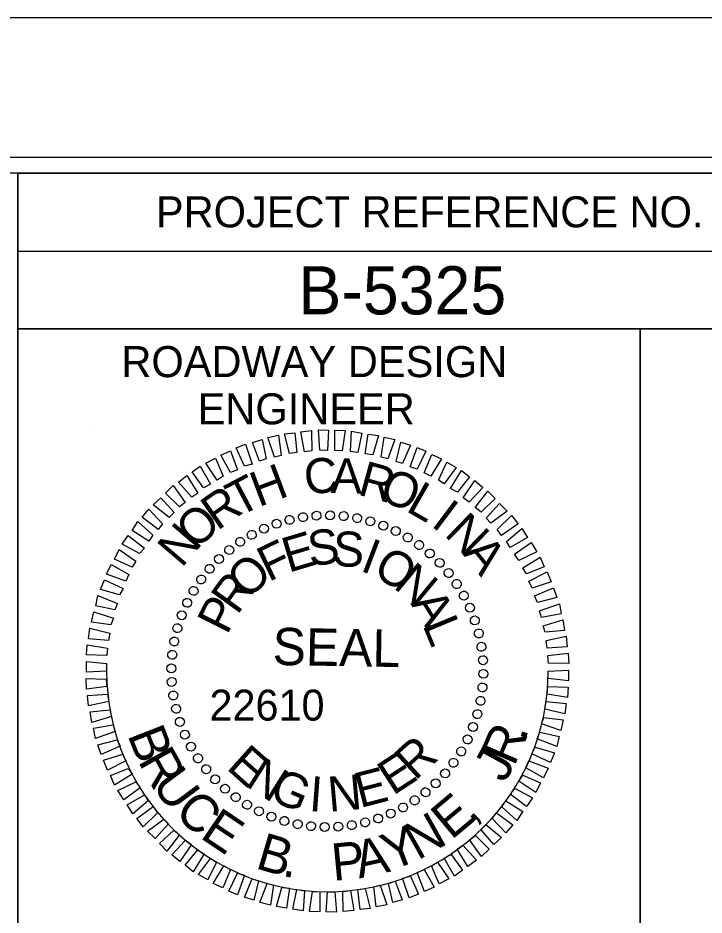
# Model space of a CAD drawing. Extents: x 10033 to 11717, y 9950 to 11050.
# Drawn here: x 11500 to 11610.3, y 10905.6 to 11050 of the extents above; entities that cross this region are included whole.
import ezdxf

# ---------------------------------------------------------------- set-up
doc = ezdxf.new("R2010")
doc.units = 0
for name, color, linetype in [('Default', 7, 'Continuous'), ('Scratch_Level_0', 7, 'Continuous'), ('Sheet Cutting Line CELL', 7, 'Continuous'), ('Sheet Data Field CELL', 7, 'Continuous'), ('Sheet PE Seal CELL', 7, 'Continuous'), ('Sheet Plot Border Inside CELL', 7, 'Continuous'), ('Sheet Plot Border Outside CELL', 7, 'Continuous'), ('Sheet Profile CELL', 7, 'Continuous'), ('Sheet Profile Grid Major CELL', 7, 'Continuous')]:
    doc.layers.add(name, color=color, linetype=linetype)

msp = doc.modelspace()

# ---------------------------------------------------------------- linework, layer by layer
at = {"layer": 'Scratch_Level_0'}
msp.add_arc((11549.72, 10944.9), 35.5, 180, 360, dxfattribs=at)
at = {"layer": 'Sheet Cutting Line CELL'}
msp.add_line((11717, 11050), (10033, 11050), dxfattribs=at)
at = {"layer": 'Sheet PE Seal CELL'}
for p, q in [((11511.62, 10984.6), (11511.62, 10984.6)), ((11545.82, 10969.65), (11545.82, 10969.65)), ((11547.97, 10969.95), (11547.97, 10969.95)), ((11550.17, 10970), (11550.17, 10970)), ((11552.37, 10969.85), (11552.37, 10969.85)), ((11554.52, 10969.5), (11554.52, 10969.5)), ((11541.52, 10968.65), (11541.52, 10968.65)), ((11543.62, 10969.25), (11543.62, 10969.25)), ((11556.62, 10969.05), (11556.62, 10969.05)), ((11558.72, 10968.35), (11558.72, 10968.35)), ((11537.57, 10966.85), (11537.57, 10966.85)), ((11539.52, 10967.85), (11539.52, 10967.85)), ((11560.72, 10967.45), (11560.72, 10967.45)), ((11535.67, 10965.7), (11535.67, 10965.7)), ((11562.67, 10966.45), (11562.67, 10966.45)), ((11564.47, 10965.2), (11564.47, 10965.2)), ((11533.92, 10964.45), (11533.92, 10964.45)), ((11566.22, 10963.85), (11566.22, 10963.85)), ((11532.27, 10962.95), (11532.27, 10962.95)), ((11567.77, 10962.35), (11567.77, 10962.35)), ((11530.77, 10961.4), (11530.77, 10961.4)), ((11529.42, 10959.65), (11529.42, 10959.65)), ((11569.27, 10960.7), (11569.27, 10960.7)), ((11570.52, 10958.95), (11570.52, 10958.95)), ((11528.17, 10957.85), (11528.17, 10957.85)), ((11571.67, 10957.05), (11571.67, 10957.05)), ((11527.17, 10955.9), (11527.17, 10955.9)), ((11572.67, 10955.1), (11572.67, 10955.1)), ((11526.27, 10953.9), (11526.27, 10953.9)), ((11573.47, 10953.1), (11573.47, 10953.1)), ((11525.57, 10951.8), (11525.57, 10951.8)), ((11574.07, 10951), (11574.07, 10951)), ((11525.12, 10949.7), (11525.12, 10949.7)), ((11574.47, 10948.8), (11574.47, 10948.8)), ((11524.77, 10947.55), (11524.77, 10947.55)), ((11574.77, 10946.65), (11574.77, 10946.65)), ((11524.62, 10945.35), (11524.62, 10945.35)), ((11549.72, 10944.9), (11549.72, 10944.9)), ((11574.82, 10944.45), (11574.82, 10944.45)), ((11524.67, 10943.15), (11524.67, 10943.15)), ((11574.67, 10942.25), (11574.67, 10942.25)), ((11524.97, 10941), (11524.97, 10941)), ((11574.32, 10940.1), (11574.32, 10940.1)), ((11525.37, 10938.8), (11525.37, 10938.8)), ((11573.87, 10938), (11573.87, 10938)), ((11525.97, 10936.7), (11525.97, 10936.7)), ((11573.17, 10935.9), (11573.17, 10935.9)), ((11526.77, 10934.7), (11526.77, 10934.7)), ((11572.27, 10933.9), (11572.27, 10933.9)), ((11527.77, 10932.75), (11527.77, 10932.75)), ((11528.92, 10930.85), (11528.92, 10930.85)), ((11571.27, 10931.95), (11571.27, 10931.95)), ((11530.17, 10929.1), (11530.17, 10929.1)), ((11570.02, 10930.15), (11570.02, 10930.15)), ((11568.67, 10928.4), (11568.67, 10928.4)), ((11531.67, 10927.45), (11531.67, 10927.45)), ((11567.17, 10926.85), (11567.17, 10926.85)), ((11533.22, 10925.95), (11533.22, 10925.95)), ((11565.52, 10925.35), (11565.52, 10925.35)), ((11534.97, 10924.6), (11534.97, 10924.6)), ((11536.77, 10923.35), (11536.77, 10923.35)), ((11563.77, 10924.1), (11563.77, 10924.1)), ((11538.72, 10922.35), (11538.72, 10922.35)), ((11559.92, 10921.95), (11559.92, 10921.95)), ((11561.87, 10922.95), (11561.87, 10922.95)), ((11540.72, 10921.45), (11540.72, 10921.45)), ((11542.82, 10920.75), (11542.82, 10920.75)), ((11555.82, 10920.55), (11555.82, 10920.55)), ((11557.92, 10921.15), (11557.92, 10921.15)), ((11544.92, 10920.3), (11544.92, 10920.3)), ((11547.07, 10919.95), (11547.07, 10919.95)), ((11549.27, 10919.8), (11549.27, 10919.8)), ((11551.47, 10919.85), (11551.47, 10919.85)), ((11553.62, 10920.15), (11553.62, 10920.15))]:
    msp.add_line(p, q, dxfattribs=at)
for points in [[(11541.22, 10979.35), (11540.17, 10982.5), (11541.87, 10982.85), (11542.27, 10979.6)], [(11543.62, 10979.9), (11542.82, 10983.1), (11544.47, 10983.25), (11544.82, 10980.05)], [(11546.02, 10980.2), (11545.47, 10983.4), (11547.17, 10983.6), (11547.22, 10980.35)], [(11548.52, 10980.45), (11548.27, 10983.7), (11549.92, 10983.65), (11549.72, 10980.4)], [(11550.92, 10980.4), (11550.92, 10983.65), (11552.57, 10983.6), (11552.12, 10980.35)], [(11553.42, 10980.25), (11553.62, 10983.5), (11555.27, 10983.2), (11554.62, 10980.05)], [(11555.82, 10979.85), (11556.27, 10983.05), (11557.92, 10982.8), (11557.02, 10979.7)], [(11558.37, 10979.3), (11558.87, 10982.55), (11560.57, 10982.15), (11559.42, 10979.05)], [(11536.37, 10977.9), (11535.07, 10980.8), (11536.57, 10981.4), (11537.62, 10978.2)], [(11538.82, 10978.7), (11537.67, 10981.7), (11539.22, 10982.15), (11539.87, 10979.05)], [(11560.77, 10978.65), (11561.52, 10981.75), (11563.07, 10981.25), (11561.82, 10978.3)], [(11534.17, 10976.85), (11532.57, 10979.65), (11534.12, 10980.35), (11535.27, 10977.3)], [(11563.02, 10977.75), (11564.17, 10980.9), (11565.57, 10980.3), (11564.17, 10977.4)], [(11565.27, 10976.8), (11566.52, 10979.75), (11568.07, 10979.05), (11566.37, 10976.25)], [(11532.02, 10975.65), (11530.17, 10978.35), (11531.72, 10979.15), (11532.97, 10976.25)], [(11567.57, 10975.65), (11568.92, 10978.5), (11570.42, 10977.65), (11568.52, 10975.05)], [(11529.82, 10974.4), (11527.97, 10976.95), (11529.27, 10977.9), (11530.92, 10975)], [(11569.52, 10974.3), (11571.27, 10977.2), (11572.57, 10976.15), (11570.62, 10973.7)], [(11527.92, 10972.9), (11525.77, 10975.3), (11527.12, 10976.35), (11528.87, 10973.55)], [(11571.57, 10972.8), (11573.42, 10975.55), (11574.72, 10974.45), (11572.52, 10972.1)], [(11525.92, 10971.35), (11523.72, 10973.55), (11524.92, 10974.75), (11526.87, 10972.05)], [(11573.47, 10971.25), (11575.52, 10973.85), (11576.72, 10972.65), (11574.42, 10970.5)], [(11524.27, 10969.6), (11521.72, 10971.65), (11522.97, 10972.8), (11525.07, 10970.4)], [(11522.52, 10967.7), (11519.92, 10969.65), (11521.02, 10970.95), (11523.22, 10968.6)], [(11575.27, 10969.5), (11577.42, 10971.85), (11578.62, 10970.65), (11576.02, 10968.7)], [(11577.02, 10967.7), (11579.32, 10969.95), (11580.37, 10968.6), (11577.72, 10966.7)], [(11521.02, 10965.8), (11518.32, 10967.5), (11519.27, 10968.95), (11521.67, 10966.75)], [(11519.52, 10963.8), (11516.72, 10965.3), (11517.72, 10966.7), (11520.32, 10964.7)], [(11578.52, 10965.75), (11580.97, 10967.85), (11581.92, 10966.4), (11579.12, 10964.8)], [(11579.82, 10963.7), (11582.47, 10965.6), (11583.42, 10964.1), (11580.52, 10962.7)], [(11518.32, 10961.65), (11515.47, 10962.9), (11516.22, 10964.45), (11518.92, 10962.6)], [(11581.12, 10961.5), (11583.92, 10963.25), (11584.57, 10961.7), (11581.72, 10960.55)], [(11517.32, 10959.35), (11514.22, 10960.5), (11514.97, 10962.05), (11517.82, 10960.45)], [(11582.12, 10959.35), (11585.07, 10960.85), (11585.72, 10959.25), (11582.62, 10958.25)], [(11516.32, 10957.15), (11513.22, 10958.05), (11513.87, 10959.6), (11516.87, 10958.2)], [(11583.02, 10957), (11586.07, 10958.3), (11586.62, 10956.75), (11583.52, 10955.95)], [(11515.57, 10954.75), (11512.47, 10955.4), (11512.82, 10957.05), (11515.97, 10955.8)], [(11583.82, 10954.6), (11587.02, 10955.75), (11587.32, 10954.1), (11584.17, 10953.55)], [(11514.92, 10952.35), (11511.82, 10952.75), (11512.17, 10954.45), (11515.32, 10953.4)], [(11584.42, 10952.2), (11587.57, 10953.15), (11587.87, 10951.45), (11584.72, 10951.15)], [(11514.52, 10949.8), (11511.32, 10950.1), (11511.52, 10951.8), (11514.77, 10951)], [(11584.87, 10949.8), (11588.12, 10950.5), (11588.27, 10948.8), (11585.07, 10948.6)], [(11514.27, 10947.4), (11511.02, 10947.5), (11511.12, 10949.15), (11514.37, 10948.6)], [(11514.22, 10944.9), (11510.97, 10944.75), (11510.97, 10946.45), (11514.22, 10946.1)], [(11585.17, 10947.4), (11588.42, 10947.8), (11588.52, 10946.1), (11585.27, 10946.2)], [(11585.22, 10944.9), (11588.47, 10945.05), (11588.47, 10943.35), (11585.22, 10943.7)], [(11514.27, 10942.4), (11511.02, 10942), (11510.92, 10943.7), (11514.17, 10943.6)], [(11585.17, 10942.4), (11588.42, 10942.3), (11588.32, 10940.65), (11585.07, 10941.2)], [(11514.57, 10940), (11511.32, 10939.3), (11511.17, 10941), (11514.37, 10941.2)], [(11584.92, 10940), (11588.12, 10939.7), (11587.92, 10938), (11584.67, 10938.8)], [(11515.02, 10937.6), (11511.87, 10936.65), (11511.57, 10938.35), (11514.72, 10938.65)], [(11584.52, 10937.45), (11587.62, 10937.05), (11587.27, 10935.35), (11584.12, 10936.4)], [(11515.62, 10935.2), (11512.42, 10934.05), (11512.12, 10935.7), (11515.27, 10936.25)], [(11583.87, 10935.05), (11586.97, 10934.4), (11586.62, 10932.75), (11583.47, 10934)], [(11516.42, 10932.8), (11513.37, 10931.5), (11512.82, 10933.05), (11515.92, 10933.85)], [(11583.12, 10932.65), (11586.22, 10931.75), (11585.57, 10930.2), (11582.57, 10931.6)], [(11517.32, 10930.45), (11514.37, 10928.95), (11513.72, 10930.55), (11516.82, 10931.55)], [(11518.32, 10928.3), (11515.52, 10926.55), (11514.87, 10928.1), (11517.72, 10929.25)], [(11582.12, 10930.45), (11585.22, 10929.3), (11584.47, 10927.75), (11581.62, 10929.35)], [(11581.12, 10928.15), (11583.97, 10926.9), (11583.22, 10925.35), (11580.52, 10927.2)], [(11519.62, 10926.1), (11516.97, 10924.2), (11516.02, 10925.7), (11518.92, 10927.1)], [(11520.92, 10924.05), (11518.47, 10921.95), (11517.52, 10923.4), (11520.32, 10925)], [(11579.92, 10926), (11582.72, 10924.5), (11581.72, 10923.1), (11579.12, 10925.1)], [(11578.42, 10924), (11581.12, 10922.3), (11580.17, 10920.85), (11577.77, 10923.05)], [(11522.42, 10922.1), (11520.12, 10919.85), (11519.07, 10921.2), (11521.72, 10923.1)], [(11576.92, 10922.1), (11579.52, 10920.15), (11578.42, 10918.85), (11576.22, 10921.2)], [(11524.17, 10920.3), (11522.02, 10917.95), (11520.82, 10919.15), (11523.42, 10921.1)], [(11525.97, 10918.55), (11523.92, 10915.95), (11522.72, 10917.15), (11525.02, 10919.3)], [(11575.17, 10920.2), (11577.72, 10918.15), (11576.47, 10917), (11574.37, 10919.4)], [(11527.87, 10917), (11526.02, 10914.25), (11524.72, 10915.35), (11526.92, 10917.7)], [(11573.52, 10918.45), (11575.72, 10916.25), (11574.52, 10915.05), (11572.57, 10917.75)], [(11529.92, 10915.5), (11528.17, 10912.6), (11526.87, 10913.65), (11528.82, 10916.1)], [(11571.52, 10916.9), (11573.67, 10914.5), (11572.32, 10913.45), (11570.57, 10916.25)], [(11531.87, 10914.15), (11530.52, 10911.3), (11529.02, 10912.15), (11530.92, 10914.75)], [(11569.62, 10915.4), (11571.47, 10912.85), (11570.17, 10911.9), (11568.52, 10914.8)], [(11534.17, 10913), (11532.92, 10910.05), (11531.37, 10910.75), (11533.07, 10913.55)], [(11567.42, 10914.15), (11569.27, 10911.45), (11567.72, 10910.65), (11566.47, 10913.55)], [(11536.42, 10912.05), (11535.27, 10908.9), (11533.87, 10909.5), (11535.27, 10912.4)], [(11563.07, 10911.9), (11564.37, 10909), (11562.87, 10908.4), (11561.82, 10911.6)], [(11565.27, 10912.95), (11566.87, 10910.15), (11565.32, 10909.45), (11564.17, 10912.5)], [(11538.67, 10911.15), (11537.92, 10908.05), (11536.37, 10908.55), (11537.62, 10911.5)], [(11541.07, 10910.5), (11540.57, 10907.25), (11538.87, 10907.65), (11540.02, 10910.75)], [(11558.22, 10910.45), (11559.27, 10907.3), (11557.57, 10906.95), (11557.17, 10910.2)], [(11560.62, 10911.1), (11561.77, 10908.1), (11560.22, 10907.65), (11559.57, 10910.75)], [(11543.62, 10909.95), (11543.17, 10906.75), (11541.52, 10907), (11542.42, 10910.1)], [(11546.02, 10909.55), (11545.82, 10906.3), (11544.17, 10906.6), (11544.82, 10909.75)], [(11548.52, 10909.4), (11548.52, 10906.15), (11546.87, 10906.2), (11547.32, 10909.45)], [(11550.92, 10909.35), (11551.17, 10906.1), (11549.52, 10906.15), (11549.72, 10909.4)], [(11553.42, 10909.6), (11553.97, 10906.4), (11552.27, 10906.2), (11552.22, 10909.45)], [(11555.82, 10909.9), (11556.62, 10906.7), (11554.97, 10906.55), (11554.62, 10909.75)]]:
    msp.add_lwpolyline(points, close=True, dxfattribs=at)
for centre, major_axis in [((11543.65, 10969.23), (-0.174, 0.699)), ((11545.8, 10969.67), (-0.113, 0.711)), ((11547.97, 10969.91), (-0.05, 0.718)), ((11550.16, 10969.97), (0.013, 0.72)), ((11552.34, 10969.84), (0.075, 0.716)), ((11554.51, 10969.51), (0.137, 0.707)), ((11556.63, 10969), (0.198, 0.692)), ((11539.52, 10967.81), (-0.293, 0.658)), ((11541.56, 10968.61), (-0.234, 0.681)), ((11558.71, 10968.31), (0.258, 0.672)), ((11560.72, 10967.44), (0.316, 0.647)), ((11537.56, 10966.83), (-0.349, 0.63)), ((11562.64, 10966.39), (0.371, 0.617)), ((11533.94, 10964.39), (-0.453, 0.56)), ((11535.7, 10965.69), (-0.403, 0.597)), ((11564.46, 10965.19), (0.423, 0.582)), ((11532.3, 10962.94), (-0.5, 0.518)), ((11566.18, 10963.82), (0.472, 0.543)), ((11567.76, 10962.32), (0.518, 0.5)), ((11530.79, 10961.35), (-0.543, 0.472)), ((11569.21, 10960.68), (0.56, 0.453)), ((11529.43, 10959.64), (-0.582, 0.423)), ((11570.51, 10958.92), (0.597, 0.403)), ((11528.22, 10957.81), (-0.617, 0.371)), ((11527.18, 10955.89), (-0.647, 0.316)), ((11571.66, 10957.05), (0.63, 0.349)), ((11572.63, 10955.1), (0.658, 0.293)), ((11526.31, 10953.88), (-0.672, 0.258)), ((11573.43, 10953.06), (0.681, 0.234)), ((11525.61, 10951.81), (-0.692, 0.198)), ((11574.06, 10950.96), (0.699, 0.174)), ((11525.1, 10949.68), (-0.707, 0.137)), ((11574.49, 10948.82), (0.711, 0.113)), ((11524.78, 10947.52), (-0.716, 0.075)), ((11574.74, 10946.65), (0.718, 0.05)), ((11524.64, 10945.33), (-0.72, 0.013)), ((11574.8, 10944.46), (0.72, -0.013)), ((11524.7, 10943.15), (-0.718, -0.05)), ((11574.66, 10942.27), (0.716, -0.075)), ((11524.95, 10940.97), (-0.711, -0.113)), ((11574.34, 10940.11), (0.707, -0.137)), ((11525.39, 10938.83), (-0.699, -0.174)), ((11573.83, 10937.98), (0.692, -0.198)), ((11526.01, 10936.73), (-0.681, -0.234)), ((11573.14, 10935.91), (0.672, -0.258)), ((11526.81, 10934.69), (-0.658, -0.293)), ((11527.79, 10932.74), (-0.63, -0.349)), ((11572.26, 10933.9), (0.647, -0.316)), ((11571.22, 10931.98), (0.617, -0.371)), ((11528.93, 10930.87), (-0.597, -0.403)), ((11570.01, 10930.15), (0.582, -0.423)), ((11530.23, 10929.11), (-0.56, -0.453)), ((11568.65, 10928.44), (0.543, -0.472)), ((11531.68, 10927.47), (-0.518, -0.5)), ((11567.14, 10926.85), (0.5, -0.518)), ((11533.27, 10925.97), (-0.472, -0.543)), ((11565.5, 10925.4), (0.453, -0.56)), ((11534.98, 10924.61), (-0.423, -0.582)), ((11563.75, 10924.1), (0.403, -0.597)), ((11536.8, 10923.4), (-0.371, -0.617)), ((11561.88, 10922.96), (0.349, -0.63)), ((11538.73, 10922.35), (-0.316, -0.647)), ((11540.73, 10921.48), (-0.258, -0.672)), ((11557.89, 10921.18), (0.234, -0.681)), ((11559.92, 10921.98), (0.293, -0.658)), ((11542.81, 10920.79), (-0.198, -0.692)), ((11544.94, 10920.28), (-0.137, -0.707)), ((11547.1, 10919.95), (-0.075, -0.716)), ((11549.28, 10919.82), (-0.013, -0.72)), ((11551.47, 10919.88), (0.05, -0.718)), ((11553.64, 10920.12), (0.113, -0.711)), ((11555.79, 10920.56), (0.174, -0.699))]:
    msp.add_ellipse(centre, major_axis=major_axis, ratio=0.999708, dxfattribs=at)
at = {"layer": 'Sheet Plot Border Inside CELL'}
msp.add_lwpolyline([(11712.5, 11027.55), (10046, 11027.55), (10046, 9972.45), (11712.5, 9972.45)], close=True, dxfattribs=at)
at = {"layer": 'Sheet Plot Border Outside CELL'}
msp.add_lwpolyline([(11717, 11050), (10033, 11050), (10033, 9950), (11717, 9950)], close=True, dxfattribs=at)
at = {"layer": 'Sheet Profile CELL'}
for p, q in [((11499.95, 11012.45), (11700, 11012.45)), ((11600, 10999.95), (11600, 10887.5))]:
    msp.add_line(p, q, dxfattribs=at)
for points in [[(11700, 11025), (10200, 11025), (10200, 9975), (11700, 9975)], [(11499.95, 11025), (11700, 11025), (11700, 10999.95), (11499.95, 10999.95)], [(11499.95, 10999.95), (11600, 10999.95), (11600, 10887.45), (11499.95, 10887.45)], [(11600, 10999.95), (11700, 10999.95), (11700, 10887.45), (11600, 10887.45)]]:
    msp.add_lwpolyline(points, close=True, dxfattribs=at)
at = {"layer": 'Sheet Profile Grid Major CELL'}
msp.add_lwpolyline([(11500, 10000), (11500, 11025), (11526.3, 11025)], dxfattribs=at)

# ---------------------------------------------------------------- texts
at = {"layer": 'Default'}
for s, rotation, p in [('B', 291.4845, (11517.53, 10934.66)), ('R', 66.6114, (11579.75, 10929.44)), ('.', 74.0916, (11581.51, 10933.48)), ('R', 299.1811, (11519.19, 10930.44)), ('J', 61.3535, (11578.21, 10926.75)), ('U', 306.6614, (11521.34, 10926.59)), ('C', 316.599, (11524.92, 10921.97)), ('E', 40.0101, (11569.65, 10917.63)), ('E', 326.1811, (11529.08, 10918.16)), ('N', 29.2842, (11564.23, 10914.39)), (',', 47.1194, (11572.88, 10920.3)), ('Y', 21.3712, (11559.89, 10912.69)), ('B', 343.4908, (11537.97, 10913.23)), ('A', 12.5309, (11554.82, 10911.51)), ('P', 5.4216, (11550.65, 10911.13)), ('.', 351.1875, (11542.32, 10911.94))]:
    msp.add_text(s, height=6, rotation=rotation, dxfattribs=at).set_placement(p)
at = {"layer": 'Sheet Data Field CELL'}
msp.add_text('B-5325', height=7.75, dxfattribs=at).set_placement((11545.06, 11002.3))
at = {"layer": 'Sheet PE Seal CELL'}
for s, height, rotation, p in [('H', 5.64, 20.6195, (11538.67, 10971.25)), ('C', 5.64, 6.2199, (11546.27, 10973.25)), ('A', 5.64, 359.0203, (11550.22, 10973.55)), ('R', 5.64, 344.6211, (11554.42, 10973.35)), ('O', 5.64, 337.4212, (11557.77, 10972.6)), ('T', 5.64, 27.8198, (11535.42, 10969.6)), ('L', 5.64, 330.2209, (11562.17, 10970.75)), ('R', 5.64, 35.0205, (11532.02, 10967.4)), ('I', 5.64, 323.0201, (11566.22, 10968.35)), ('O', 5.64, 42.2217, (11528.57, 10964.3)), ('N', 5.64, 315.8189, (11568.37, 10966.8)), ('N', 5.64, 49.4235, (11526.27, 10961.4)), ('E', 5.64, 16.6111, (11543.47, 10960.7)), ('S', 5.64, 7.2556, (11546.92, 10961.75)), ('S', 5.64, 357.9004, (11550.52, 10961.8)), ('F', 5.64, 25.967, (11540.27, 10959.2)), ('I', 5.64, 339.1896, (11554.82, 10961.1)), ('A', 5.64, 308.6172, (11571.32, 10963.85)), ('O', 5.64, 329.8335, (11556.82, 10960.4)), ('O', 5.64, 44.6812, (11536.97, 10956.25)), ('N', 5.64, 320.4766, (11560.17, 10958.4)), ('R', 5.64, 54.0397, (11535.22, 10953.8)), ('P', 5.64, 63.3989, (11533.62, 10950.6)), ('A', 5.64, 301.7603, (11563.02, 10955.8)), ('L', 5.64, 292.4008, (11564.97, 10952.35)), ('SEAL', 5.998, 359, (11540.87, 10945.9)), ('R', 5.64, 42.4814, (11563.82, 10927.15)), ('E', 5.64, 318.2769, (11533.32, 10929.25)), ('E', 5.64, 33.1241, (11560.27, 10924.8)), ('N', 5.64, 327.634, (11536.32, 10926.55)), ('E', 5.64, 14.4118, (11554.97, 10922.85)), ('G', 5.64, 336.9902, (11540.12, 10924.3)), ('I', 5.64, 355.7012, (11546.67, 10922.4)), ('N', 5.64, 5.0564, (11550.02, 10922.25))]:
    msp.add_text(s, height=height, rotation=rotation, dxfattribs=at).set_placement(p)
msp.add_text('   22610  ', height=4.975, dxfattribs=at).set_placement((11525.22, 10936.94))
at = {"layer": 'Sheet Profile CELL'}
for s, height, p in [('PROJECT REFERENCE NO.', 5.0001, (11522.15, 11016.3)), ('ROADWAY DESIGN', 5.0001, (11516.6, 10992.2)), ('ENGINEER', 5, (11528.85, 10984.6))]:
    msp.add_text(s, height=height, dxfattribs=at).set_placement(p)

doc.saveas('drawing.dxf')
